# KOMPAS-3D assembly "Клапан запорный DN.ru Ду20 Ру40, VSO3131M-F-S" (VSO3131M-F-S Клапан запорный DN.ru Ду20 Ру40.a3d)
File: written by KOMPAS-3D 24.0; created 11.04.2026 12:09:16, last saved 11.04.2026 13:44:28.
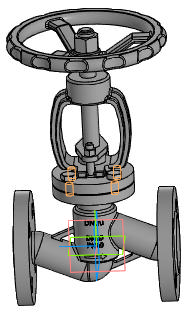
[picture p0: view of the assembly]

Document properties: Автор: R2D2; Полное имя файла: E:\Работа\Зайцев\VSO3131M-F-S Клапан запорный DN.ru Ду15-100 Ру40\DN20\исходные материалы\VSO3131M-F-S Клапан запорный DN.ru Ду20 Ру40.a3d

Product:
- Component [detail]: Корпус  | qty 1  | pos. 1  | Масса: 6.9; Автор: R2D2; source file: Корпус.m3d
- Component [detail]: Сборка  | qty 1  | pos. 2  | Масса: 1.44705; Автор: R2D2; source file: 2.m3d
- Component [standard]: Hexagon head screw ISO 4017 - М8 x 16  | qty 4  | Масса: 0.012085; Раздел спецификации: Стандартные изделия; Рассекать на разрезах: no
- Part/product: Клапан запорный DN.ru Ду20 Ру40  | designation VSO3131M-F-S
    Масса: 5.15
    Раздел спецификации: Прочие изделия
    Примечание: D090-02138

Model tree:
1. Эскиз:2  (with: Ребро.Элемент вращения:2, Ребро.Операция без истории:1, Грань.Элемент вращения:2)
2. Элемент вращения:1
     Угол 1 = 360
3. Эскиз:3  (with: Ребро.Операция без истории:1)
4. Элемент выдавливания:2
     Расстояние 1 = 27
5. Зеркальный массив:1
6. Экземпляр ( 1 )
7. Экземпляр ( 2 )  (with: Элемент выдавливания:2)
8. Массив по концентрической сетке:1  (with: Грань.Элемент вращения:2, Грань.Операция без истории:1)  (labels: Грань.Элемент выдавливания:9.Экземпляр ( 1, 2 ); Труба@/Нестандартная труба@/L = 73.6 мм; Труба@/Нестандартная труба@/L = 89.3 мм)  (4 pattern instances)
     Шаг 2 = 360

Referenced files in E:\Работа\Зайцев\VSO3131M-F-S Клапан запорный DN.ru Ду15-100 Ру40\DN20\исходные материалы\: Корпус.m3d, 2.m3d
Referenced files in C:\Program Files\ASCON\KOMPAS-3D v24\Libs\PolynomLib\DATA\vault\Methods\Kompas\3D\: PLib_Bolt_1_ISO_1100.m3d
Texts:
  Hexagon head screw
  BOSimple***PART:17775d1c-e7de-f283-40f0-d40789f7f59e***SHORTLOC:A259_7B16EF33AB1642D2[13;1,25;16;8;-;Undefined]
  Программные изделия  и базы данных
  VSO3131M-F-S
  Hexagon head screw ISO 4017 - М8 x 16 (1)
  hole1
  hole2
  Hexagon head screw ISO 4017 - М8 x 16 (2)
  Hexagon head screw ISO 4017 - М8 x 16 (3)
  Hexagon head screw ISO 4017 - М8 x 16 (4)
  Ось Z.Начало координат
  Ось Y.Начало координат
  Плоскость XY.Начало координат
  Плоскость ZY.Начало координат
